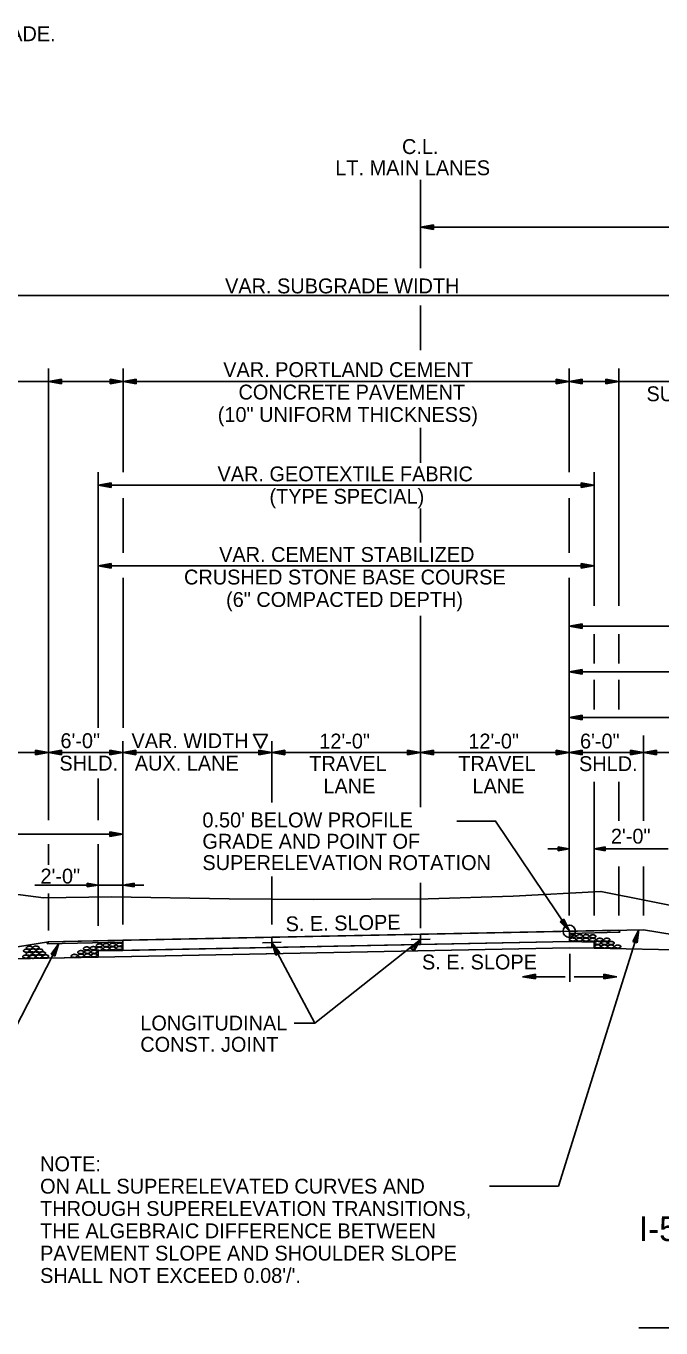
# Model space of a CAD drawing. Extents: x 1734743 to 1735935, y 759845 to 763831.
# Drawn here: x 1735677.2 to 1735728.4, y 760010.9 to 760115.9 of the extents above; entities that cross this region are included whole.
import ezdxf

# ---------------------------------------------------------------- set-up
doc = ezdxf.new("R2010")
doc.units = 0
for name, color, linetype in [('1', 7, 'Continuous'), ('10', 7, 'Continuous'), ('19', 7, 'Continuous'), ('8', 7, 'Continuous'), ('9', 7, 'Continuous'), ('Level 1', 7, 'Continuous'), ('R_Draft', 7, 'Continuous'), ('R_Prop Surface', 7, 'Continuous')]:
    doc.layers.add(name, color=color, linetype=linetype)

# ---------------------------------------------------------------- blocks, each defined once
blk = doc.blocks.new('TM')
at = {"layer": '8'}
for p, q in [((-120.309, 21.181), (-119.787, -20.829)), ((0, 0), (-120.309, 21.181)), ((-31.382, 2.945), (-120.176, 10.512)), ((-119.787, -20.829), (0, 0)), ((-119.911, -10.826), (-31.307, -3.057))]:
    blk.add_line(p, q, dxfattribs=at)
blk = doc.blocks.new('ROCKS')
at = {"layer": '1'}
blk.add_spline([(0.013, 0.06), (0.053, 0.053), (0.107, 0.033), (0.133, 0.013), (0.133, -0.007), (0.12, -0.033), (0.107, -0.04), (0.073, -0.053), (0.033, -0.067), (0.013, -0.067), (-0.02, -0.06), (-0.06, -0.053), (-0.087, -0.047), (-0.113, -0.02), (-0.113, -0.007), (-0.107, 0.02), (-0.087, 0.033), (-0.067, 0.047), (-0.033, 0.053), (-0.02, 0.06), (0.013, 0.06)], degree=3, dxfattribs=at)

msp = doc.modelspace()

# ---------------------------------------------------------------- linework, layer by layer
at = {"layer": '1'}
msp.add_line((1735726.59, 760010.94), (1735798.51, 760010.94), dxfattribs=at)
at = {"layer": '10'}
msp.add_lwpolyline([(1735696.62, 760058.81), (1735696.06, 760057.69), (1735695.49, 760058.81)], close=True, dxfattribs=at)
at = {"layer": '19'}
for p, q in [((1735708.97, 760096.4), (1735708.97, 760103.55)), ((1735710.02, 760099.91), (1735708.97, 760099.72)), ((1735708.97, 760099.72), (1735760.97, 760099.72)), ((1735708.97, 760099.72), (1735710.02, 760099.54)), ((1735710.02, 760099.81), (1735709.25, 760099.75)), ((1735709.25, 760099.7), (1735710.02, 760099.63)), ((1735710.02, 760099.54), (1735710.02, 760099.91)), ((1735669.86, 760094.2), (1735737.69, 760094.2)), ((1735708.97, 760089.81), (1735708.97, 760093.39)), ((1735678.96, 760058.26), (1735678.96, 760088.31)), ((1735684.98, 760079.95), (1735684.98, 760088.31)), ((1735720.97, 760079.95), (1735720.97, 760088.31)), ((1735724.97, 760069.18), (1735724.97, 760088.31)), ((1735643.1, 760087.27), (1735678.96, 760087.27)), ((1735680.01, 760087.45), (1735678.96, 760087.27)), ((1735684.98, 760087.27), (1735678.96, 760087.27)), ((1735678.96, 760087.27), (1735680.01, 760087.08)), ((1735680.01, 760087.35), (1735679.24, 760087.29)), ((1735679.24, 760087.24), (1735680.01, 760087.17)), ((1735680.01, 760087.08), (1735680.01, 760087.45)), ((1735683.93, 760087.45), (1735683.93, 760087.08)), ((1735684.98, 760087.27), (1735683.93, 760087.45)), ((1735684.7, 760087.29), (1735683.93, 760087.35)), ((1735683.93, 760087.08), (1735684.98, 760087.27)), ((1735683.93, 760087.17), (1735684.7, 760087.24)), ((1735686.03, 760087.45), (1735684.98, 760087.27)), ((1735684.98, 760087.27), (1735686.03, 760087.08)), ((1735720.97, 760087.27), (1735684.98, 760087.27)), ((1735686.03, 760087.35), (1735685.26, 760087.29)), ((1735685.26, 760087.24), (1735686.03, 760087.17)), ((1735686.03, 760087.08), (1735686.03, 760087.45)), ((1735719.92, 760087.45), (1735719.92, 760087.08)), ((1735720.97, 760087.27), (1735719.92, 760087.45)), ((1735720.69, 760087.29), (1735719.92, 760087.35)), ((1735719.92, 760087.08), (1735720.97, 760087.27)), ((1735719.92, 760087.17), (1735720.69, 760087.24)), ((1735722.02, 760087.45), (1735720.97, 760087.27)), ((1735724.97, 760087.27), (1735720.97, 760087.27)), ((1735720.97, 760087.27), (1735722.02, 760087.08)), ((1735722.02, 760087.35), (1735721.25, 760087.29)), ((1735721.25, 760087.24), (1735722.02, 760087.17)), ((1735722.02, 760087.08), (1735722.02, 760087.45)), ((1735723.92, 760087.45), (1735723.92, 760087.08)), ((1735724.97, 760087.27), (1735723.92, 760087.45)), ((1735724.69, 760087.29), (1735723.92, 760087.35)), ((1735723.92, 760087.08), (1735724.97, 760087.27)), ((1735723.92, 760087.17), (1735724.69, 760087.24)), ((1735724.97, 760087.27), (1735749.18, 760087.27)), ((1735708.97, 760080.7), (1735708.97, 760083.54)), ((1735682.98, 760059.34), (1735682.98, 760079.95)), ((1735684.03, 760079.09), (1735682.98, 760078.91)), ((1735684.03, 760078.72), (1735684.03, 760079.09)), ((1735721.92, 760079.09), (1735721.92, 760078.72)), ((1735722.97, 760078.91), (1735721.92, 760079.09)), ((1735722.97, 760069.18), (1735722.97, 760079.95)), ((1735682.98, 760078.91), (1735722.97, 760078.91)), ((1735682.98, 760078.91), (1735684.03, 760078.72)), ((1735684.03, 760079), (1735683.26, 760078.93)), ((1735683.26, 760078.88), (1735684.03, 760078.81)), ((1735722.69, 760078.93), (1735721.92, 760079)), ((1735721.92, 760078.72), (1735722.97, 760078.91)), ((1735721.92, 760078.81), (1735722.69, 760078.88)), ((1735684.98, 760073.45), (1735684.98, 760077.86)), ((1735708.97, 760074.3), (1735708.97, 760077.02)), ((1735720.97, 760073.45), (1735720.97, 760077.86)), ((1735684.03, 760072.59), (1735682.98, 760072.41)), ((1735682.98, 760072.41), (1735722.97, 760072.41)), ((1735682.98, 760072.41), (1735684.03, 760072.22)), ((1735684.03, 760072.49), (1735683.26, 760072.43)), ((1735683.26, 760072.38), (1735684.03, 760072.31)), ((1735684.03, 760072.22), (1735684.03, 760072.59)), ((1735721.92, 760072.59), (1735721.92, 760072.22)), ((1735722.97, 760072.41), (1735721.92, 760072.59)), ((1735722.69, 760072.43), (1735721.92, 760072.49)), ((1735721.92, 760072.22), (1735722.97, 760072.41)), ((1735721.92, 760072.31), (1735722.69, 760072.38)), ((1735684.98, 760059.34), (1735684.98, 760071.44)), ((1735720.97, 760068.2), (1735720.97, 760071.45)), ((1735708.97, 760052.94), (1735708.97, 760068.36)), ((1735720.97, 760060.17), (1735720.97, 760068.2)), ((1735722.02, 760067.73), (1735720.97, 760067.54)), ((1735720.97, 760067.54), (1735800.97, 760067.54)), ((1735720.97, 760067.54), (1735722.02, 760067.36)), ((1735722.02, 760067.63), (1735721.25, 760067.57)), ((1735722.02, 760067.36), (1735722.02, 760067.73)), ((1735721.25, 760067.52), (1735722.02, 760067.45)), ((1735722.99, 760064.52), (1735722.99, 760066.89)), ((1735724.98, 760064.52), (1735724.98, 760066.89)), ((1735722.02, 760064.04), (1735720.97, 760063.86)), ((1735720.97, 760063.86), (1735722.02, 760063.67)), ((1735720.97, 760063.86), (1735760.97, 760063.86)), ((1735722.02, 760063.95), (1735721.25, 760063.88)), ((1735721.25, 760063.83), (1735722.02, 760063.76)), ((1735722.02, 760063.67), (1735722.02, 760064.04)), ((1735722.99, 760060.83), (1735722.99, 760063.2)), ((1735724.98, 760060.83), (1735724.98, 760063.2)), ((1735722.02, 760060.35), (1735720.97, 760060.17)), ((1735722.02, 760060.26), (1735721.25, 760060.2)), ((1735722.02, 760059.99), (1735722.02, 760060.35)), ((1735720.97, 760060.17), (1735722.02, 760059.99)), ((1735720.97, 760060.17), (1735750.97, 760060.17)), ((1735720.97, 760044.19), (1735720.97, 760060.17)), ((1735721.25, 760060.14), (1735722.02, 760060.07)), ((1735678.96, 760051.89), (1735678.96, 760058.26)), ((1735684.97, 760043.48), (1735684.97, 760058.26)), ((1735696.97, 760053.32), (1735696.97, 760058.26)), ((1735726.97, 760051.83), (1735726.97, 760058.72)), ((1735677.91, 760057.53), (1735677.91, 760057.17)), ((1735678.96, 760057.35), (1735677.91, 760057.53)), ((1735678.68, 760057.38), (1735677.91, 760057.44)), ((1735677.91, 760057.17), (1735678.96, 760057.35)), ((1735677.91, 760057.25), (1735678.68, 760057.32)), ((1735680.01, 760057.53), (1735678.96, 760057.35)), ((1735678.96, 760057.35), (1735680.01, 760057.17)), ((1735678.97, 760057.35), (1735684.97, 760057.35)), ((1735680.01, 760057.44), (1735679.24, 760057.38)), ((1735679.24, 760057.32), (1735680.01, 760057.25)), ((1735680.01, 760057.17), (1735680.01, 760057.53)), ((1735683.92, 760057.53), (1735683.92, 760057.17)), ((1735684.97, 760057.35), (1735683.92, 760057.53)), ((1735684.69, 760057.38), (1735683.92, 760057.44)), ((1735683.92, 760057.17), (1735684.97, 760057.35)), ((1735683.92, 760057.25), (1735684.69, 760057.32)), ((1735686.02, 760057.53), (1735684.97, 760057.35)), ((1735696.97, 760057.35), (1735684.97, 760057.35)), ((1735684.97, 760057.35), (1735686.02, 760057.17)), ((1735686.02, 760057.44), (1735685.25, 760057.38)), ((1735685.25, 760057.32), (1735686.02, 760057.25)), ((1735686.02, 760057.17), (1735686.02, 760057.53)), ((1735695.92, 760057.53), (1735695.92, 760057.17)), ((1735696.97, 760057.35), (1735695.92, 760057.53)), ((1735696.69, 760057.38), (1735695.92, 760057.44)), ((1735695.92, 760057.17), (1735696.97, 760057.35)), ((1735695.92, 760057.25), (1735696.69, 760057.32)), ((1735698.02, 760057.53), (1735696.97, 760057.35)), ((1735696.97, 760057.35), (1735708.97, 760057.35)), ((1735696.97, 760057.35), (1735698.02, 760057.17)), ((1735698.02, 760057.44), (1735697.25, 760057.38)), ((1735697.25, 760057.32), (1735698.02, 760057.25)), ((1735698.02, 760057.17), (1735698.02, 760057.53)), ((1735707.92, 760057.53), (1735707.92, 760057.17)), ((1735708.97, 760057.35), (1735707.92, 760057.53)), ((1735708.69, 760057.38), (1735707.92, 760057.44)), ((1735707.92, 760057.17), (1735708.97, 760057.35)), ((1735707.92, 760057.25), (1735708.69, 760057.32)), ((1735710.02, 760057.53), (1735708.97, 760057.35)), ((1735708.97, 760057.35), (1735720.97, 760057.35)), ((1735708.97, 760057.35), (1735710.02, 760057.17)), ((1735710.02, 760057.44), (1735709.25, 760057.38)), ((1735709.25, 760057.32), (1735710.02, 760057.25)), ((1735710.02, 760057.17), (1735710.02, 760057.53)), ((1735719.92, 760057.53), (1735719.92, 760057.17)), ((1735720.97, 760057.35), (1735719.92, 760057.53)), ((1735720.69, 760057.38), (1735719.92, 760057.44)), ((1735719.92, 760057.17), (1735720.97, 760057.35)), ((1735719.92, 760057.25), (1735720.69, 760057.32)), ((1735722.02, 760057.53), (1735720.97, 760057.35)), ((1735720.97, 760057.35), (1735726.97, 760057.35)), ((1735720.97, 760057.35), (1735722.02, 760057.17)), ((1735722.02, 760057.44), (1735721.25, 760057.38)), ((1735721.25, 760057.32), (1735722.02, 760057.25)), ((1735722.02, 760057.17), (1735722.02, 760057.53)), ((1735725.92, 760057.53), (1735725.92, 760057.17)), ((1735726.97, 760057.35), (1735725.92, 760057.53)), ((1735726.69, 760057.38), (1735725.92, 760057.44)), ((1735725.92, 760057.17), (1735726.97, 760057.35)), ((1735725.92, 760057.25), (1735726.69, 760057.32)), ((1735728.02, 760057.53), (1735726.97, 760057.35)), ((1735726.97, 760057.35), (1735728.02, 760057.17)), ((1735728.02, 760057.44), (1735727.25, 760057.38)), ((1735727.25, 760057.32), (1735728.02, 760057.25)), ((1735728.02, 760057.17), (1735728.02, 760057.53)), ((1735682.98, 760051.89), (1735682.98, 760055.26)), ((1735722.99, 760044.19), (1735722.99, 760054.98)), ((1735724.98, 760051.83), (1735724.98, 760054.98)), ((1735655.23, 760050.77), (1735684.96, 760050.77)), ((1735683.91, 760050.95), (1735683.91, 760050.58)), ((1735684.96, 760050.77), (1735683.91, 760050.95)), ((1735684.68, 760050.79), (1735683.91, 760050.85)), ((1735683.91, 760050.58), (1735684.96, 760050.77)), ((1735678.96, 760048.28), (1735678.96, 760049.95)), ((1735682.98, 760043.37), (1735682.98, 760049.95)), ((1735683.91, 760050.67), (1735684.68, 760050.74)), ((1735720.07, 760049.74), (1735720.07, 760049.43)), ((1735720.97, 760049.58), (1735720.07, 760049.74)), ((1735723.88, 760049.74), (1735722.99, 760049.58)), ((1735723.88, 760049.43), (1735723.88, 760049.74)), ((1735719.25, 760049.58), (1735720.97, 760049.58)), ((1735720.73, 760049.6), (1735720.07, 760049.66)), ((1735720.07, 760049.43), (1735720.97, 760049.58)), ((1735720.07, 760049.5), (1735720.73, 760049.56)), ((1735722.99, 760049.58), (1735723.88, 760049.43)), ((1735722.99, 760049.58), (1735728.95, 760049.58)), ((1735723.88, 760049.67), (1735723.23, 760049.61)), ((1735723.23, 760049.56), (1735723.88, 760049.51)), ((1735724.98, 760044.19), (1735724.98, 760048.16)), ((1735726.97, 760044.19), (1735726.97, 760048.16)), ((1735677.87, 760046.66), (1735682.98, 760046.66)), ((1735679.86, 760046.66), (1735686.66, 760046.66)), ((1735682.08, 760046.82), (1735682.08, 760046.51)), ((1735682.98, 760046.66), (1735682.08, 760046.82)), ((1735682.74, 760046.68), (1735682.08, 760046.74)), ((1735682.08, 760046.51), (1735682.98, 760046.66)), ((1735682.08, 760046.58), (1735682.74, 760046.64)), ((1735685.87, 760046.82), (1735684.98, 760046.66)), ((1735684.98, 760046.66), (1735685.87, 760046.51)), ((1735685.87, 760046.74), (1735685.22, 760046.69)), ((1735685.22, 760046.64), (1735685.87, 760046.59)), ((1735685.87, 760046.51), (1735685.87, 760046.82)), ((1735696.97, 760043.48), (1735696.97, 760047.35)), ((1735708.97, 760043.19), (1735708.97, 760046.83)), ((1735678.96, 760043), (1735678.96, 760045.97)), ((1735720.54, 760043.91), (1735720.24, 760043.7)), ((1735720.24, 760043.7), (1735720.98, 760042.93)), ((1735720.31, 760043.75), (1735720.8, 760043.15)), ((1735720.84, 760043.17), (1735720.47, 760043.85)), ((1735720.98, 760042.93), (1735720.54, 760043.91)), ((1735726.96, 760043.05), (1735678.96, 760042.09)), ((1735720.98, 760042.93), (1735720.98, 760042.1)), ((1735725.06, 760042.85), (1735720.98, 760042.76)), ((1735726.09, 760042.1), (1735726.58, 760043.04)), ((1735726.18, 760042.07), (1735726.47, 760042.79)), ((1735726.52, 760042.77), (1735726.35, 760042.02)), ((1735726.58, 760043.04), (1735726.44, 760041.99)), ((1735726.96, 760043.05), (1735737.69, 760041.26)), ((1735720.98, 760041.6), (1735666.45, 760040.51)), ((1735678.96, 760042.09), (1735669.86, 760040.58)), ((1735684.97, 760042.04), (1735678.87, 760041.92)), ((1735679.81, 760041.94), (1735679.17, 760041.09)), ((1735679.67, 760041.7), (1735679.25, 760041.05)), ((1735679.42, 760040.97), (1735679.71, 760041.68)), ((1735679.49, 760040.93), (1735679.81, 760041.94)), ((1735720.98, 760041.6), (1735682.97, 760040.84)), ((1735684.97, 760041.38), (1735682.97, 760041.34)), ((1735682.97, 760041.34), (1735682.97, 760040.84)), ((1735684.97, 760042.21), (1735684.97, 760041.38)), ((1735720.98, 760042.1), (1735684.97, 760041.38)), ((1735697.62, 760041.19), (1735696.97, 760042.02)), ((1735696.97, 760042.02), (1735697.3, 760041.01)), ((1735697.08, 760041.77), (1735697.38, 760041.06)), ((1735697.55, 760041.15), (1735697.13, 760041.79)), ((1735708.97, 760042.28), (1735708.17, 760041.58)), ((1735708.17, 760041.58), (1735708.45, 760041.35)), ((1735708.78, 760042.07), (1735708.24, 760041.52)), ((1735708.39, 760041.4), (1735708.82, 760042.04)), ((1735708.45, 760041.35), (1735708.97, 760042.28)), ((1735720.98, 760042.1), (1735722.98, 760042.06)), ((1735720.98, 760041.6), (1735722.98, 760041.56)), ((1735720.98, 760041.6), (1735722.97, 760041.56)), ((1735722.97, 760041.56), (1735741.1, 760041.2)), ((1735722.98, 760042.06), (1735722.98, 760041.56)), ((1735722.98, 760041.56), (1735737.69, 760041.26)), ((1735726.44, 760041.99), (1735726.09, 760042.1)), ((1735682.97, 760040.84), (1735669.86, 760040.58)), ((1735679.17, 760041.09), (1735679.49, 760040.93)), ((1735697.3, 760041.01), (1735697.62, 760041.19)), ((1735721.01, 760041.1), (1735721.01, 760038.85)), ((1735720.63, 760039.26), (1735717.21, 760039.26)), ((1735721.38, 760039.26), (1735724.81, 760039.26))]:
    msp.add_line(p, q, dxfattribs=at)
for points in [[(1735613.49, 760045.48), (1735663.07, 760045.8), (1735674.62, 760046.14), (1735678.57, 760045.64), (1735684.05, 760045.7), (1735693.53, 760045.56), (1735700.38, 760045.49), (1735709.58, 760045.54), (1735716.45, 760045.77)], [(1735716.45, 760045.77), (1735723.53, 760046.14), (1735735.42, 760043.76), (1735749.01, 760038.66), (1735762.35, 760036.78)], [(1735725.06, 760042.85), (1735720.98, 760042.76), (1735720.98, 760042.76), (1735720.98, 760042.93), (1735720.98, 760042.93), (1735720.98, 760042.93), (1735724.96, 760043.01), (1735724.96, 760043.01), (1735724.96, 760043.01), (1735725.06, 760042.85), (1735725.06, 760042.85), (1735725.06, 760042.85)], [(1735684.97, 760042.04), (1735678.87, 760041.92), (1735678.87, 760041.92), (1735678.96, 760042.09), (1735678.96, 760042.09), (1735678.96, 760042.09), (1735684.97, 760042.21), (1735684.97, 760042.21), (1735684.97, 760042.21), (1735684.97, 760042.04), (1735684.97, 760042.04), (1735684.97, 760042.04)], [(1735682.97, 760040.84), (1735682.97, 760041.34), (1735720.98, 760042.1), (1735722.98, 760042.06), (1735722.98, 760041.56), (1735722.98, 760041.56), (1735722.98, 760041.56), (1735720.98, 760041.6), (1735682.97, 760040.84)], [(1735700.45, 760035.53), (1735700.45, 760035.53), (1735696.97, 760042.02)], [(1735698.79, 760035.53), (1735700.45, 760035.53), (1735708.97, 760042.28)]]:
    msp.add_lwpolyline(points, dxfattribs=at)
msp.add_lwpolyline([(1735720.98, 760042.93), (1735684.97, 760042.21), (1735684.97, 760041.38), (1735720.98, 760042.1)], close=True, dxfattribs=at)
msp.add_circle((1735720.97, 760042.93), 0.5, dxfattribs=at)
at = {"layer": '9'}
for p, q in [((1735669.86, 760057.35), (1735678.96, 760057.35)), ((1735726.97, 760057.35), (1735737.69, 760057.35)), ((1735726.58, 760043.04), (1735725.08, 760038.26)), ((1735679.81, 760041.94), (1735670.11, 760023.16)), ((1735725.08, 760038.26), (1735720.09, 760022.37))]:
    msp.add_line(p, q, dxfattribs=at)
for points in [[(1735711.9, 760051.82), (1735715.03, 760051.82), (1735720.98, 760042.93)], [(1735714.54, 760022.37), (1735720.09, 760022.37)]]:
    msp.add_lwpolyline(points, dxfattribs=at)
at = {"layer": 'R_Draft'}
for p, q in [((1735696.97, 760042.4), (1735696.97, 760041.65)), ((1735708.97, 760042.65), (1735708.97, 760041.9)), ((1735697.74, 760042.04), (1735696.22, 760042.01)), ((1735709.74, 760042.29), (1735708.22, 760042.26))]:
    msp.add_line(p, q, dxfattribs=at)
at = {"layer": 'R_Prop Surface'}
for p, q in [((1735724.96, 760043.01), (1735725.06, 760042.85)), ((1735678.96, 760042.09), (1735678.87, 760041.92))]:
    msp.add_line(p, q, dxfattribs=at)

# ---------------------------------------------------------------- block references
at = {"layer": '19', "xscale": 0.008761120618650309}
for p, yscale, rotation in [((1735717.2, 760039.26), -0.008761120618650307, -179.20057588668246), ((1735724.81, 760039.26), 0.008761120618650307, -0.7994241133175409)]:
    msp.add_blockref('TM', p, dxfattribs=dict(at, yscale=yscale, rotation=rotation))
at = {"layer": 'Level 1'}
for p, xscale, yscale, rotation in [((1735721.24, 760042.27), 2.011654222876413, 2.011654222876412, 1.33680650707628), ((1735721.24, 760042.55), 2.011654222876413, 2.011654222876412, 1.33680650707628), ((1735721.79, 760042.54), 2.011654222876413, 2.011654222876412, 1.33680650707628), ((1735721.78, 760042.26), 2.011654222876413, 2.011654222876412, 1.33680650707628), ((1735722.3, 760042.26), 2.011654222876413, 2.011654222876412, 1.33680650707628), ((1735722.31, 760042.54), 2.011654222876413, 2.011654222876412, 1.33680650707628), ((1735722.84, 760042.25), 2.011654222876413, 2.011654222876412, 1.33680650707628), ((1735722.85, 760042.53), 2.011654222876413, 2.011654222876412, 1.33680650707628), ((1735723.41, 760042.25), 2.011654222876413, 2.011654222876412, 1.33680650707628), ((1735723.98, 760042.25), 2.011654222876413, 2.011654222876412, 1.33680650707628), ((1735677.18, 760041.37), 2.011654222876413, 2.011654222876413, 1.8263814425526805), ((1735677.42, 760041.61), 2.011654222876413, 2.011654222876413, 1.8263814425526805), ((1735677.71, 760041.39), 2.011654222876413, 2.011654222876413, 1.8263814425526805), ((1735677.94, 760041.62), 2.011654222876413, 2.011654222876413, 1.8263814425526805), ((1735678.23, 760041.38), 2.011654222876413, 2.011654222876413, 1.8263814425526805), ((1735678.46, 760041.16), 2.011654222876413, 2.011654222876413, 1.8263814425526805), ((1735681.56, 760041.25), 2.0116542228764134, 2.011654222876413, 3.8532744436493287), ((1735682.02, 760041.55), 2.0116542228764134, 2.011654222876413, 3.8532744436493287), ((1735682.09, 760041.27), 2.0116542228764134, 2.011654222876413, 3.8532744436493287), ((1735682.55, 760041.57), 2.0116542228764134, 2.011654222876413, 3.8532744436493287), ((1735682.63, 760041.28), 2.0116542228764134, 2.011654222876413, 3.8532744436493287), ((1735683.06, 760041.8), 2.0116542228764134, 2.011654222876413, 3.8532744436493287), ((1735683.06, 760041.52), 2.0116542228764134, 2.011654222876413, 3.8532744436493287), ((1735683.6, 760041.82), 2.0116542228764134, 2.011654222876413, 3.8532744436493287), ((1735683.61, 760041.54), 2.0116542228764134, 2.011654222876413, 3.8532744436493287), ((1735684.12, 760041.84), 2.0116542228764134, 2.011654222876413, 3.8532744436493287), ((1735684.13, 760041.56), 2.0116542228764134, 2.011654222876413, 3.8532744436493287), ((1735684.67, 760041.86), 2.0116542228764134, 2.011654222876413, 3.8532744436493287), ((1735684.67, 760041.58), 2.0116542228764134, 2.011654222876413, 3.8532744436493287), ((1735723.25, 760041.72), 2.011654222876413, 2.011654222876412, 1.33680650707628), ((1735723.26, 760042), 2.011654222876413, 2.011654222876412, 1.33680650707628), ((1735723.8, 760041.71), 2.011654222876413, 2.011654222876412, 1.33680650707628), ((1735723.8, 760041.99), 2.011654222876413, 2.011654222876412, 1.33680650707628), ((1735724.33, 760041.99), 2.011654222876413, 2.011654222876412, 1.33680650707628), ((1735724.32, 760041.71), 2.011654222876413, 2.011654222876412, 1.33680650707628), ((1735724.86, 760041.7), 2.011654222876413, 2.011654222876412, 1.33680650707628), ((1735677.12, 760040.89), 2.011654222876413, 2.011654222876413, 1.8263814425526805), ((1735677.4, 760041.12), 2.011654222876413, 2.011654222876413, 1.8263814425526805), ((1735677.66, 760040.88), 2.011654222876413, 2.011654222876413, 1.8263814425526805), ((1735677.93, 760041.14), 2.011654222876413, 2.011654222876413, 1.8263814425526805), ((1735678.19, 760040.9), 2.011654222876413, 2.011654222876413, 1.8263814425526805), ((1735678.71, 760040.91), 2.011654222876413, 2.011654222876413, 1.8263814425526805), ((1735681.03, 760040.95), 2.0116542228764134, 2.011654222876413, 3.8532744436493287), ((1735681.57, 760040.97), 2.0116542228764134, 2.011654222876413, 3.8532744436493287), ((1735682.09, 760040.99), 2.0116542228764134, 2.011654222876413, 3.8532744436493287), ((1735682.63, 760041), 2.0116542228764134, 2.011654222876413, 3.8532744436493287)]:
    msp.add_blockref('ROCKS', p, dxfattribs=dict(at, xscale=xscale, yscale=yscale, rotation=rotation))

# ---------------------------------------------------------------- texts
at = {"layer": '1'}
msp.add_text('PROFILE GRADE SHOWN ON PLAN AND PROFILE SHEETS IS 22" ABOVE SUBGRADE.', height=1.2, dxfattribs=at).set_placement((1735613.79, 760114.72))
at = {"layer": '10'}
for s, height, p in [("0.50' BELOW PROFILE ", 1.2, (1735691.38, 760051.31)), ('GRADE AND POINT OF', 1.2, (1735691.38, 760049.59)), ('SUPERELEVATION ROTATION  ', 1.2, (1735691.38, 760047.87)), ('S. E. SLOPE', 1.2, (1735709.09, 760039.85)), ('NOTE:', 1.2, (1735678.29, 760023.57)), ('ON ALL SUPERELEVATED CURVES AND', 1.2, (1735678.29, 760021.77)), ('THROUGH SUPERELEVATION TRANSITIONS,', 1.2, (1735678.29, 760019.97)), ('THE ALGEBRAIC DIFFERENCE BETWEEN', 1.2, (1735678.29, 760018.17)), ('I-57 TYPICAL DIVIDED HIGHWAY SUPERELEVATED', 2, (1735726.59, 760017.94)), ('PAVEMENT SLOPE AND SHOULDER SLOPE', 1.2, (1735678.29, 760016.37)), ("SHALL NOT EXCEED 0.08'/'.", 1.2, (1735678.29, 760014.57))]:
    msp.add_text(s, height=height, dxfattribs=at).set_placement(p)
msp.add_text('S. E. SLOPE', height=1.2, rotation=0.9769, dxfattribs=at).set_placement((1735698.1, 760042.92))
at = {"layer": '19'}
for s, p in [('C.L.', (1735707.48, 760105.62)), ('LT. MAIN LANES', (1735702.1, 760103.91)), ('VAR. SUBGRADE WIDTH', (1735693.21, 760094.38)), ('VAR. PORTLAND CEMENT', (1735693.06, 760087.63)), ('CONCRETE PAVEMENT', (1735694.29, 760085.82)), ('SURFACE COURSE (1/2")', (1735727.2, 760085.68)), ('(10" UNIFORM THICKNESS)', (1735692.62, 760084.01)), ('VAR. GEOTEXTILE FABRIC', (1735692.6, 760079.22)), ('(TYPE SPECIAL)', (1735696.79, 760077.41)), ('VAR. CEMENT STABILIZED ', (1735692.73, 760072.72)), ('CRUSHED STONE BASE COURSE', (1735689.9, 760070.9)), ('(6" COMPACTED DEPTH)', (1735693.29, 760069.09)), ('6\'-0"', (1735679.93, 760057.7)), ('VAR. WIDTH ', (1735685.66, 760057.7)), ('12\'-0"', (1735700.81, 760057.67)), ('12\'-0"', (1735712.83, 760057.67)), ('6\'-0"', (1735721.84, 760057.67)), ('SHLD.', (1735679.85, 760055.89)), ('AUX. LANE', (1735685.93, 760055.89)), ('TRAVEL', (1735700, 760055.86)), ('TRAVEL', (1735712.02, 760055.86)), ('SHLD.', (1735721.76, 760055.85)), ('LANE', (1735701.14, 760054.05)), ('LANE', (1735713.16, 760054.05)), ('2\'-0"', (1735724.33, 760050)), ('2\'-0"', (1735678.32, 760046.78)), ('LONGITUDINAL', (1735686.37, 760034.93)), ('CONST. JOINT', (1735686.37, 760033.21))]:
    msp.add_text(s, height=1.2, dxfattribs=at).set_placement(p)

doc.saveas('drawing.dxf')
